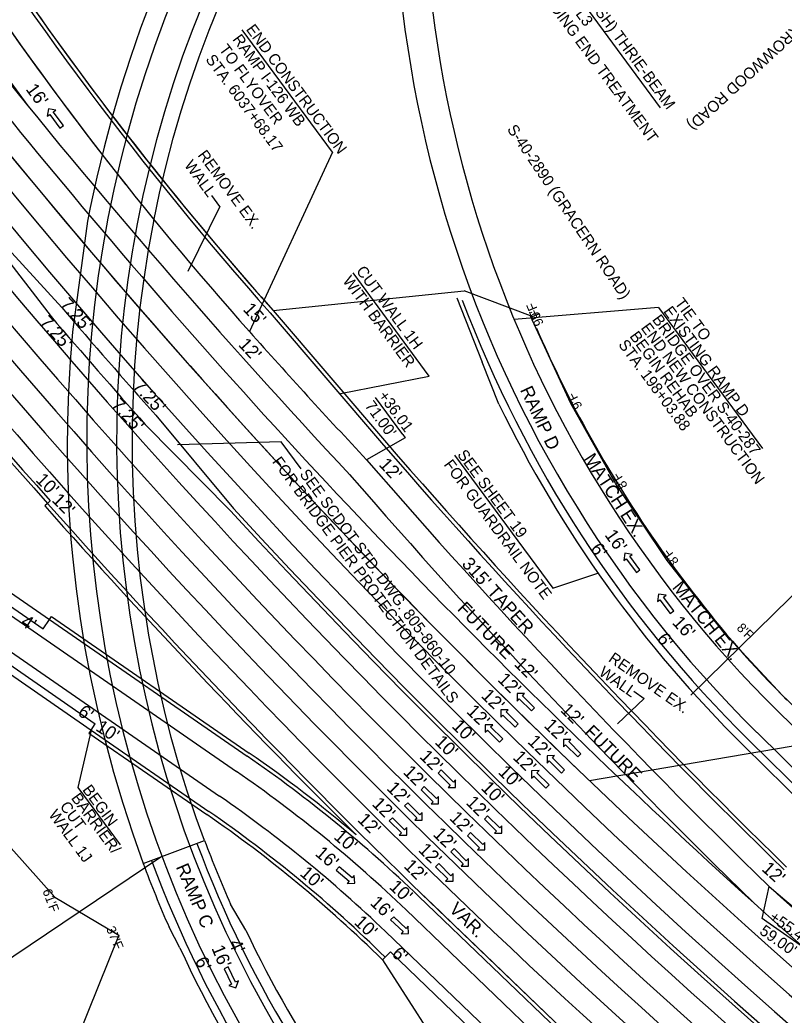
# Model space of a CAD drawing. Extents: x 1966090 to 1975830, y 788086 to 801233.
# Drawn here: x 1971374 to 1971783, y 795345 to 795878 of the extents above; entities that cross this region are included whole.
import ezdxf

# ---------------------------------------------------------------- set-up
doc = ezdxf.new("R2010")
doc.units = 0
for name, color, linetype in [('BR_PRESTRESSED BEAM', 7, 'Continuous'), ('BR_PROPOSED_DRAINAGE', 7, 'Continuous'), ('BR_REBAR', 7, 'Continuous'), ('RD_AR_03', 7, 'Continuous'), ('RD_EX_Driveway_txCode', 7, 'Continuous'), ('RD_EX_RW_TX', 7, 'Continuous'), ('RD_EX_SU_Gas', 7, 'Continuous'), ('RD_PD_PaveShd', 7, 'Continuous'), ('RD_Sketch1', 7, 'Continuous'), ('RD_Sketch6', 7, 'Continuous'), ('RD_Sketch8', 7, 'Continuous'), ('RD_Sketch9', 7, 'Continuous')]:
    doc.layers.add(name, color=color, linetype=linetype)

msp = doc.modelspace()

# ---------------------------------------------------------------- linework, layer by layer
at = {"layer": 'BR_PRESTRESSED BEAM'}
for p, q in [((1971607.64, 795728.69), (1971621.28, 795694.3)), ((1971630.21, 795671.8), (1971621.28, 795694.3)), ((1971294.77, 795621.86), (1971389.49, 795556.41)), ((1971274.3, 795592.24), (1971411.8, 795497.23)), ((1971761.39, 795488.77), (1971857.56, 795393.97)), ((1971494.64, 795390.02), (1971486.49, 795403.91)), ((1971459.35, 795380.49), (1971453.56, 795391.6))]:
    msp.add_line(p, q, dxfattribs=at)
for centre, radius, start, end in [((1974296, 798203.94), 3890.72, 216.39766, 221.64292), ((1972226.58, 795960.7), 662.66, 205.84668, 225.41147), ((1972046.23, 795651.96), 612.24, 200.44722, 203.90048), ((1972046.23, 795651.96), 647.33, 200.45023, 203.7159), ((1972046.23, 795651.96), 610.62, 205.40179, 241.4237), ((1972046.23, 795651.96), 646.62, 204.8235, 241.40446)]:
    msp.add_arc(centre, radius, start, end, dxfattribs=at)
at = {"layer": 'BR_PROPOSED_DRAINAGE'}
for p, q in [((1971509.25, 795722.05), (1971611.55, 795732.56)), ((1971647.1, 795719.12), (1971611.55, 795732.56)), ((1971648.01, 795716.93), (1971647.1, 795719.12)), ((1971668.63, 795672.14), (1971648.01, 795716.93)), ((1971692.82, 795629.15), (1971668.63, 795672.14)), ((1971720.24, 795588.12), (1971692.82, 795629.15)), ((1971750.82, 795549.37), (1971720.24, 795588.12)), ((1971750.82, 795549.37), (1971784.46, 795513.22)), ((1971392.31, 795407.67), (1971321.63, 795487.28)), ((1971392.31, 795407.67), (1971426.71, 795387.29)), ((1971426.71, 795387.29), (1971399.12, 795319.1))]:
    msp.add_line(p, q, dxfattribs=at)
msp.add_arc((1972855.69, 796921.19), 1803, 214.9213, 221.68841, dxfattribs=at)
at = {"layer": 'BR_REBAR'}
for p, q in [((1971507.76, 795720.72), (1971568.41, 795649.85)), ((1971509.25, 795722.05), (1971569.92, 795651.16))]:
    msp.add_line(p, q, dxfattribs=at)
for centre, radius, start, end in [((1972855.69, 796921.19), 1805, 211.88652, 221.68841), ((1972855.69, 796921.19), 1803, 211.88652, 221.68841), ((1974398.08, 798103.05), 3745.03, 220.92379, 225.70896), ((1974398.08, 798103.05), 3743.03, 220.92379, 225.70786)]:
    msp.add_arc(centre, radius, start, end, dxfattribs=at)
at = {"layer": 'RD_AR_03'}
msp.add_lwpolyline([(1971442.82, 795885.31), (1971438.26, 795873.18), (1971432.83, 795857.45), (1971427.78, 795841.59), (1971423.1, 795825.63), (1971418.8, 795809.55), (1971414.89, 795793.38), (1971411.36, 795777.11), (1971409.92, 795769.91), (1971401.88, 795710.54), (1971400.57, 795694.68), (1971399.66, 795678.79), (1971399.15, 795662.88), (1971399.03, 795646.96), (1971399.3, 795631.05), (1971399.97, 795615.14), (1971401.03, 795599.26), (1971401.95, 795588.71), (1971403.75, 795572.82), (1971405.94, 795556.97), (1971408.52, 795541.18), (1971411.49, 795525.47), (1971414.84, 795509.82), (1971418.58, 795494.27), (1971422.7, 795478.81), (1971423.87, 795474.69), (1971428.84, 795458.07), (1971434.19, 795441.56), (1971439.69, 795425.78), (1971472.56, 795438.08), (1971468.07, 795450.29), (1971463.25, 795464.47), (1971458.8, 795478.77), (1971454.74, 795493.19), (1971451.05, 795507.7), (1971447.75, 795522.31), (1971444.83, 795537), (1971442.79, 795548.15), (1971440.35, 795563.37), (1971438.3, 795578.65), (1971436.63, 795593.98), (1971435.37, 795609.34), (1971434.49, 795624.74), (1971434.02, 795640.14), (1971433.93, 795655.56), (1971434, 795661.42), (1971434.44, 795676.97), (1971435.28, 795692.52), (1971436.52, 795708.03), (1971438.14, 795723.51), (1971440.16, 795738.94), (1971442.57, 795754.32), (1971445.37, 795769.63), (1971445.43, 795769.92), (1971448.51, 795784.82), (1971451.98, 795799.63), (1971455.83, 795814.35), (1971460.06, 795828.97), (1971464.67, 795843.47), (1971469.66, 795857.84), (1971475.01, 795872.08), (1971480.73, 795886.18)], dxfattribs=at)
at = {"layer": 'RD_EX_Driveway_txCode'}
for points in [[(1971395.11, 795819.59), (1971397.04, 795821.02), (1971391.58, 795828.39), (1971392.89, 795829.36), (1971388.93, 795829.95), (1971388.34, 795825.99), (1971389.65, 795826.96)], [(1971703.8, 795581.57), (1971705.73, 795582.98), (1971700.32, 795590.38), (1971701.63, 795591.35), (1971697.68, 795591.96), (1971697.07, 795588.01), (1971698.38, 795588.97)], [(1971721.87, 795559.64), (1971723.8, 795561.05), (1971718.39, 795568.46), (1971719.7, 795569.42), (1971715.75, 795570.03), (1971715.14, 795566.08), (1971716.45, 795567.04)], [(1971647.63, 795507.46), (1971649.32, 795509.17), (1971642.81, 795515.62), (1971643.95, 795516.78), (1971639.95, 795516.76), (1971639.97, 795512.76), (1971641.12, 795513.91)], [(1971638.84, 795498.81), (1971640.53, 795500.51), (1971634.02, 795506.97), (1971635.16, 795508.12), (1971631.16, 795508.1), (1971631.18, 795504.1), (1971632.33, 795505.26)], [(1971630.57, 795490.77), (1971632.26, 795492.47), (1971625.74, 795498.92), (1971626.89, 795500.08), (1971622.89, 795500.06), (1971622.91, 795496.06), (1971624.06, 795497.22)], [(1971672.45, 795482.87), (1971674.14, 795484.57), (1971667.62, 795491.02), (1971668.77, 795492.18), (1971664.77, 795492.16), (1971664.79, 795488.16), (1971665.93, 795489.32)], [(1971663.66, 795474.21), (1971665.35, 795475.92), (1971658.83, 795482.37), (1971659.97, 795483.53), (1971655.97, 795483.51), (1971655.99, 795479.51), (1971657.14, 795480.67)], [(1971599.29, 795475.85), (1971597.6, 795474.14), (1971604.12, 795467.69), (1971602.97, 795466.53), (1971606.97, 795466.55), (1971606.95, 795470.55), (1971605.81, 795469.4)], [(1971655.39, 795466.17), (1971657.08, 795467.87), (1971650.56, 795474.33), (1971651.7, 795475.48), (1971647.7, 795475.46), (1971647.72, 795471.46), (1971648.87, 795472.62)], [(1971590.21, 795466.96), (1971588.52, 795465.25), (1971595.04, 795458.8), (1971593.89, 795457.64), (1971597.89, 795457.66), (1971597.87, 795461.66), (1971596.73, 795460.51)], [(1971581.42, 795458.31), (1971579.73, 795456.6), (1971586.25, 795450.15), (1971585.1, 795448.99), (1971589.1, 795449.01), (1971589.08, 795453.01), (1971587.94, 795451.85)], [(1971573.15, 795450.26), (1971571.46, 795448.56), (1971577.98, 795442.1), (1971576.83, 795440.95), (1971580.83, 795440.97), (1971580.81, 795444.97), (1971579.67, 795443.81)], [(1971624.1, 795451.25), (1971622.42, 795449.55), (1971628.93, 795443.09), (1971627.79, 795441.94), (1971631.79, 795441.96), (1971631.77, 795445.96), (1971630.62, 795444.8)], [(1971615.02, 795442.36), (1971613.34, 795440.66), (1971619.85, 795434.2), (1971618.71, 795433.05), (1971622.71, 795433.07), (1971622.69, 795437.07), (1971621.54, 795435.91)], [(1971606.23, 795433.71), (1971604.54, 795432), (1971611.06, 795425.55), (1971609.92, 795424.39), (1971613.92, 795424.41), (1971613.9, 795428.41), (1971612.75, 795427.26)], [(1971597.96, 795425.67), (1971596.27, 795423.96), (1971602.79, 795417.51), (1971601.65, 795416.35), (1971605.65, 795416.37), (1971605.63, 795420.37), (1971604.48, 795419.21)], [(1971544.69, 795424.05), (1971543.11, 795422.24), (1971550.04, 795416.23), (1971548.97, 795415), (1971552.96, 795415.28), (1971552.68, 795419.27), (1971551.61, 795418.04)], [(1971573.86, 795397.25), (1971572.23, 795395.5), (1971578.95, 795389.25), (1971577.84, 795388.06), (1971581.83, 795388.21), (1971581.69, 795392.2), (1971580.58, 795391.01)], [(1971485.14, 795370.41), (1971482.99, 795369.34), (1971487.06, 795361.12), (1971485.6, 795360.4), (1971489.39, 795359.12), (1971490.67, 795362.91), (1971489.21, 795362.19)]]:
    msp.add_lwpolyline(points, close=True, dxfattribs=at)
at = {"layer": 'RD_EX_SU_Gas'}
for radius, start, end in [(3784.72, 216.39766, 226.1479), (3784.72, 216.39766, 236.97136), (3796.72, 216.39766, 236.97136), (3842.72, 216.39766, 244.09898), (3854.72, 216.39766, 243.9112), (3866.72, 216.9932, 243.9112), (3772.72, 227.89927, 236.25939)]:
    msp.add_arc((1974296, 798203.94), radius, start, end, dxfattribs=at)
at = {"layer": 'RD_PD_PaveShd'}
for p, q in [((1971350.67, 795770.24), (1971390.42, 795718.68)), ((1971352.19, 795771.54), (1971396.11, 795723.57)), ((1971507.76, 795720.72), (1971568.41, 795649.85)), ((1971446.44, 795665.91), (1971488.03, 795615.91)), ((1971486.53, 795614.58), (1971440.84, 795660.92)), ((1971389.89, 795620.01), (1971388.46, 795618.61)), ((1971291.36, 795616.92), (1971386.08, 795551.47)), ((1971276.58, 795595.53), (1971414.07, 795500.52)), ((1971386.08, 795551.47), (1971389.49, 795556.41)), ((1971389.49, 795556.41), (1971495.36, 795483.25)), ((1971411.8, 795497.23), (1971414.07, 795500.52)), ((1971411.8, 795497.23), (1971474.89, 795453.64)), ((1971764.19, 795491.62), (1971799.86, 795456.47)), ((1971587.39, 795408.1), (1971750.1, 795251.91)), ((1971613.52, 795385.79), (1971751.49, 795253.35)), ((1971572.09, 795378.42), (1971569.24, 795375.53)), ((1971572.09, 795378.42), (1971727.94, 795228.82))]:
    msp.add_line(p, q, dxfattribs=at)
for centre, radius, start, end in [((1972855.69, 796921.19), 1805, 211.88652, 221.68841), ((1974296, 798203.94), 3888.72, 216.39766, 221.6415), ((1972226.58, 795960.7), 658.66, 200.72662, 225.41147), ((1974296, 798203.94), 3823.47, 220.54169, 221.69067), ((1974296, 798203.94), 3815.97, 220.5414, 221.69067), ((1972226.58, 795960.7), 627.43, 203.29542, 208.85724), ((1972271.31, 795985.34), 678.5, 208.85724, 221.68144), ((1974398.08, 798103.05), 3745.03, 220.92379, 225.70896), ((1974296, 798203.94), 3890.72, 221.64292, 226.41296), ((1974296, 798203.94), 3820.72, 222.66541, 243.9112), ((1974296, 798203.94), 3818.72, 222.66592, 243.9112), ((1972190.25, 795924.25), 577.4, 222.50253, 230.41518), ((1971073.56, 794872.81), 742, 46.17145, 55.35655), ((1971073.56, 794872.81), 706, 45.40382, 55.35655), ((1972046.23, 795651.96), 616.62, 200.44761, 245.71509), ((1972046.23, 795651.96), 642.62, 200.44985, 245.71509), ((1974194.95, 798281.36), 3752.57, 229.84039, 235.24659)]:
    msp.add_arc(centre, radius, start, end, dxfattribs=at)
at = {"layer": 'RD_Sketch1'}
msp.add_arc((1972855.69, 796921.19), 1820, 209.01045, 218.45481, dxfattribs=at)
at = {"layer": 'RD_Sketch6'}
for p, q in [((1971618.5, 795963.59), (1971716.63, 795830.48)), ((1971541.05, 795806.86), (1971492.76, 795872.37)), ((1971541.05, 795806.86), (1971496.56, 795710.75)), ((1971480.72, 795777.76), (1971476.44, 795783.56)), ((1971480.72, 795777.76), (1971463.55, 795742.94)), ((1971592.91, 795686.88), (1971552.15, 795742.17)), ((1971715.65, 795723.66), (1971638.38, 795717.07)), ((1971715.65, 795723.66), (1971771.42, 795648.01)), ((1971545.43, 795677.59), (1971592.91, 795686.88)), ((1971578.69, 795655.59), (1971564.14, 795675.32)), ((1971890.82, 795670.85), (1971732.93, 795516)), ((1971513.63, 795651.57), (1971458, 795650.03)), ((1971524.22, 795637.2), (1971513.63, 795651.57)), ((1971606.45, 795644.41), (1971659.02, 795573.26)), ((1971659.02, 795573.26), (1971683.26, 795581.33)), ((1971678.64, 795470.16), (1972172.12, 795554.73)), ((1971702.46, 795518.13), (1971708.05, 795514.21)), ((1971708.05, 795514.21), (1971693.69, 795500.54)), ((1971411.8, 795497.23), (1971404.67, 795466.54)), ((1971404.67, 795466.54), (1971427.39, 795435.72)), ((1971449.73, 795429.54), (1971351.85, 795363.71)), ((1971795.19, 795379.39), (1971773.59, 795394.56))]:
    msp.add_line(p, q, dxfattribs=at)
for points in [[(1971578.69, 795655.59), (1971580, 795653.8), (1971559.34, 795641.99)], [(1971773.59, 795394.56), (1971771.21, 795396.23), (1971774.85, 795413.46)], [(1971567.84, 795374.1), (1971606.59, 795313.8), (1971691.73, 795253.72)]]:
    msp.add_lwpolyline(points, dxfattribs=at)
at = {"layer": 'RD_Sketch8'}
for p, q in [((1971289.08, 795613.63), (1971489.67, 795475.03)), ((1971279.99, 795600.47), (1971480.58, 795461.86)), ((1971779.64, 795507.29), (1972107.79, 795183.82)), ((1972094.93, 795174.03), (1971768.41, 795495.9)), ((1971580.47, 795400.88), (1971743.18, 795244.69)), ((1971569.39, 795389.34), (1971732.1, 795233.15))]:
    msp.add_line(p, q, dxfattribs=at)
for centre, radius, start, end in [((1972855.69, 796921.19), 1820, 205.76109, 221.68841), ((1972855.69, 796921.19), 1836, 205.76109, 216.40394), ((1972226.58, 795960.7), 652.66, 167.91315, 225.41147), ((1972226.58, 795960.7), 636.66, 170.70317, 225.41147), ((1974296, 798203.94), 3772.72, 216.39766, 219.89735), ((1974296, 798203.94), 3808.72, 216.39766, 236.97136), ((1974296, 798203.94), 3830.72, 216.39766, 243.9112), ((1972046.23, 795651.96), 636.62, 156.21044, 245.71509), ((1974296, 798203.94), 3878.72, 216.39766, 241.30888), ((1972046.23, 795651.96), 620.62, 156.21044, 245.71509), ((1974296, 798203.94), 3760.72, 218.51982, 223.11151), ((1974296, 798203.94), 3772.72, 219.89735, 227.89927), ((1974296, 798203.94), 3748.72, 221.68841, 223.11151), ((1974398.08, 798103.05), 3757.03, 220.92379, 225.71558), ((1974398.08, 798103.05), 3769.03, 220.92379, 225.71906), ((1971073.56, 794872.81), 732, 46.17145, 55.35655), ((1971073.56, 794872.81), 716, 46.17145, 55.35655), ((1974296, 798203.94), 3760.72, 227.90275, 236.17378)]:
    msp.add_arc(centre, radius, start, end, dxfattribs=at)
at = {"layer": 'RD_Sketch9'}
for p, q in [((1971388.46, 795618.61), (1971386.97, 795617.28)), ((1971389.49, 795556.4), (1971390.63, 795558.05)), ((1971389.49, 795556.41), (1971495.36, 795483.25)), ((1971390.63, 795558.05), (1971496.5, 795484.9)), ((1971411.8, 795497.23), (1971410.66, 795495.59)), ((1971410.66, 795495.59), (1971473.76, 795451.99)), ((1971411.8, 795497.23), (1971474.89, 795453.64)), ((1971588.78, 795409.54), (1971751.49, 795253.35)), ((1971587.39, 795408.1), (1971750.1, 795251.91)), ((1971569.24, 795375.53), (1971567.84, 795374.1))]:
    msp.add_line(p, q, dxfattribs=at)
for centre, radius, start, end in [((1974296, 798203.94), 3892.72, 221.64292, 225.21479), ((1974296, 798203.94), 3890.72, 221.64292, 226.41296), ((1971073.56, 794872.81), 744, 49.80058, 55.35655), ((1971073.56, 794872.81), 742, 46.17145, 55.35655), ((1971073.56, 794872.81), 704, 45.40382, 55.35655), ((1971073.56, 794872.81), 706, 45.40382, 55.35655)]:
    msp.add_arc(centre, radius, start, end, dxfattribs=at)

# ---------------------------------------------------------------- texts
at = {"layer": 'RD_EX_Driveway_txCode'}
for s, height, rotation, p in [('S-40-287 (ARROWWOOD ROAD)', 5.9996, 222.6982, (1971820.63, 795905.2)), ("16'", 7, 306.3501, (1971376.54, 795840.45)), ('S-40-2890 (GRACERN ROAD)', 5.9996, 304.0248, (1971634.33, 795819.07)), ("7.25'", 7, 312.7111, (1971394.64, 795724.89)), ("15'", 7, 312.6866, (1971492.8, 795722.29)), ("7.25'", 7, 312.7111, (1971383.82, 795715.29)), ("12'", 7, 312.6866, (1971490.29, 795703.4)), ("7.25'", 7, 312.7111, (1971433.7, 795681)), ('RAMP D', 7, 295.2025, (1971641.41, 795679.48)), ("7.25'", 7, 312.7111, (1971422.2, 795671.03)), ('MATCH EX.', 7, 302.9708, (1971675.32, 795642.61)), ("12'", 7, 312.6866, (1971565.55, 795639.16)), ("10'", 7, 315.2852, (1971381.68, 795630.77)), ("12'", 7, 315.2852, (1971390.34, 795619.93)), ("16'", 7, 305.6636, (1971686.56, 795601.69)), ("6'", 7, 305.6636, (1971678.92, 795594.35)), ("315' TAPER", 7, 312.3484, (1971609.92, 795585.89)), ('MATCH EX.', 7, 308.9536, (1971722.7, 795573.49)), ('FUTURE', 7, 314.2849, (1971607.52, 795561.8)), ("4'", 7, 326.2427, (1971373.6, 795553.74)), ("16'", 7, 312.4911, (1971722.63, 795554.52)), ("6'", 7, 305.6636, (1971714.44, 795546.16)), ("12'", 7, 315.2836, (1971637.93, 795532.11)), ("12'", 7, 315.2836, (1971629.11, 795523.83)), ("12'", 7, 315.2836, (1971620.31, 795515.18)), ("12'", 7, 315.2836, (1971662.74, 795507.51)), ("6'", 7, 322.6442, (1971404.13, 795505.79)), ("12'", 7, 315.2836, (1971612.45, 795506.79)), ("10'", 7, 326.4769, (1971413.8, 795497.35)), ("10'", 7, 315.2852, (1971604.57, 795498.85)), ("12'", 7, 315.2836, (1971653.92, 795499.24)), ('FUTURE', 7, 315.2836, (1971675.61, 795495.7)), ("10'", 7, 315.2852, (1971595.41, 795490.37)), ("12'", 7, 315.2836, (1971645.13, 795490.58)), ("12'", 7, 315.2836, (1971587.31, 795482.53)), ("12'", 7, 315.2836, (1971637.26, 795482.19)), ("12'", 7, 315.2836, (1971578.49, 795474.25)), ("10'", 7, 315.2852, (1971629.38, 795474.26)), ("12'", 7, 315.2836, (1971569.7, 795465.6)), ("10'", 7, 315.2852, (1971620.22, 795465.77)), ("12'", 7, 315.2836, (1971561.83, 795457.21)), ("12'", 7, 315.2836, (1971612.12, 795457.93)), ("12'", 7, 315.2852, (1971554.07, 795448.72)), ("12'", 7, 315.2836, (1971603.3, 795449.65)), ("10'", 7, 319.0439, (1971541.31, 795439.41)), ("12'", 7, 315.2836, (1971594.51, 795441)), ("12'", 7, 315.2836, (1971586.65, 795432.61)), ("16'", 7, 319.0439, (1971531.36, 795430.45)), ('RAMP C', 7, 292.9652, (1971457.11, 795423.96)), ("12'", 7, 315.2852, (1971578.81, 795423.94)), ("12'", 7, 318.3026, (1971770.47, 795422.27)), ("10'", 7, 319.0439, (1971523.17, 795419.76)), ("10'", 7, 317.1039, (1971571, 795412.71)), ("16'", 7, 317.1039, (1971560.76, 795404.09)), ('VAR.', 7, 315.2852, (1971603.15, 795400.77)), ("10'", 7, 317.1039, (1971552.21, 795393.69)), ("4'", 7, 294.4163, (1971485.36, 795383.24)), ("16'", 7, 292.3379, (1971476.16, 795380.45)), ("6'", 7, 315.8299, (1971572.36, 795376.91)), ("6'", 7, 295.5545, (1971467.2, 795373.76))]:
    msp.add_text(s, height=height, rotation=rotation, dxfattribs=at).set_placement(p)
at = {"layer": 'RD_EX_RW_TX'}
for s, rotation, p in [("9'F", 112.4987, (1971652.81, 795718.41)), ("9'F", 112.847, (1971654.28, 795714.92)), ("9'F", 117.3467, (1971675.04, 795670.63)), ("8'F", 121.8464, (1971699.33, 795628.15)), ("8'F", 126.3461, (1971726.81, 795587.63)), ("8'F", 316.3214, (1971757.18, 795551.45)), ("61'F", 290.4844, (1971385.69, 795411.12)), ("37'F", 293.1333, (1971419.75, 795390.87))]:
    msp.add_text(s, height=5, rotation=rotation, dxfattribs=at).set_placement(p)
at = {"layer": 'RD_Sketch6'}
for s, height, rotation, p in [('CONSTRUCT MTBBC3 (MASH) THRIE-BEAM', 5.9996, 306.4243, (1971620.8, 795963.95)), ('BARRIER CONNECTOR TL3', 5.9996, 306.4243, (1971613.56, 795958.61)), ('CONSTRUCT MT2 LEADING END TREATMENT', 5.9996, 306.4243, (1971606.32, 795953.26)), ('END CONSTRUCTION', 5.9996, 306.5592, (1971494.5, 795872.53)), ('RAMP I-126 WB ', 5.9996, 306.5592, (1971487.27, 795867.17)), ('TO FLYOVER', 6, 306.5592, (1971480.04, 795861.81)), ('STA. 6037+68.17', 5.9996, 306.5592, (1971472.82, 795856.45)), ('REMOVE EX. ', 5.9996, 306.5574, (1971468.65, 795805.13)), ('WALL', 6, 306.5574, (1971461.42, 795799.77)), ('CUT WALL 1H', 5.9996, 306.5574, (1971553.46, 795743.14)), ('WITH BARRIER', 5.9996, 306.5574, (1971546.24, 795737.78)), ('TIE TO ', 6, 306.3977, (1971724.06, 795725.95)), ('EXISTING RAMP D', 6, 306.3977, (1971718.02, 795721.5)), ('BRIDGE OVER S-40-287', 6, 306.3977, (1971711.99, 795717.05)), ('END NEW CONSTRUCTION', 6, 306.3977, (1971705.95, 795712.6)), ('BEGIN REHAB', 6, 306.3977, (1971699.91, 795708.15)), ('STA. 198+03.88', 6, 306.3977, (1971693.88, 795703.69)), ('+36.01', 6, 306.3977, (1971565.35, 795676.21)), ("71.00'", 6, 306.3977, (1971558.1, 795670.87)), ('FOR BRIDGE PIER PROTECTION DETAILS', 6, 306.396, (1971508.54, 795640.9)), ('SEE SHEET 19', 5.9996, 306.4867, (1971607.62, 795644.71)), ('FOR GUARDRAIL NOTE', 5.9996, 306.4867, (1971600.38, 795639.36)), ('SEE SCDOT STD. DWG. 805-860-10', 6, 306.396, (1971523.2, 795634.28)), ('REMOVE EX.', 6, 325.0834, (1971688.42, 795534.39)), ('WALL', 6, 325.0834, (1971683.27, 795527.01)), ('BEGIN ', 6, 306.3977, (1971406.87, 795465.2)), ('BARRIER/', 6, 306.3977, (1971400.84, 795460.75)), ('CUT ', 6, 306.3977, (1971394.8, 795456.3)), ('WALL 1J', 6, 306.3977, (1971388.76, 795451.85)), ('+55.43', 6, 324.9236, (1971774.46, 795395.79)), ("59.00'", 6, 324.9236, (1971769.28, 795388.42))]:
    msp.add_text(s, height=height, rotation=rotation, dxfattribs=at).set_placement(p)

doc.saveas('drawing.dxf')
